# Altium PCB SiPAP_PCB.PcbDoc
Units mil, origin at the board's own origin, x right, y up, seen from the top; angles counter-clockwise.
Board outline 4000 x 3000 mil, 2 copper layers (Top Layer, Bottom Layer); 76 components, 74 nets, 268 pads, 135 vias.
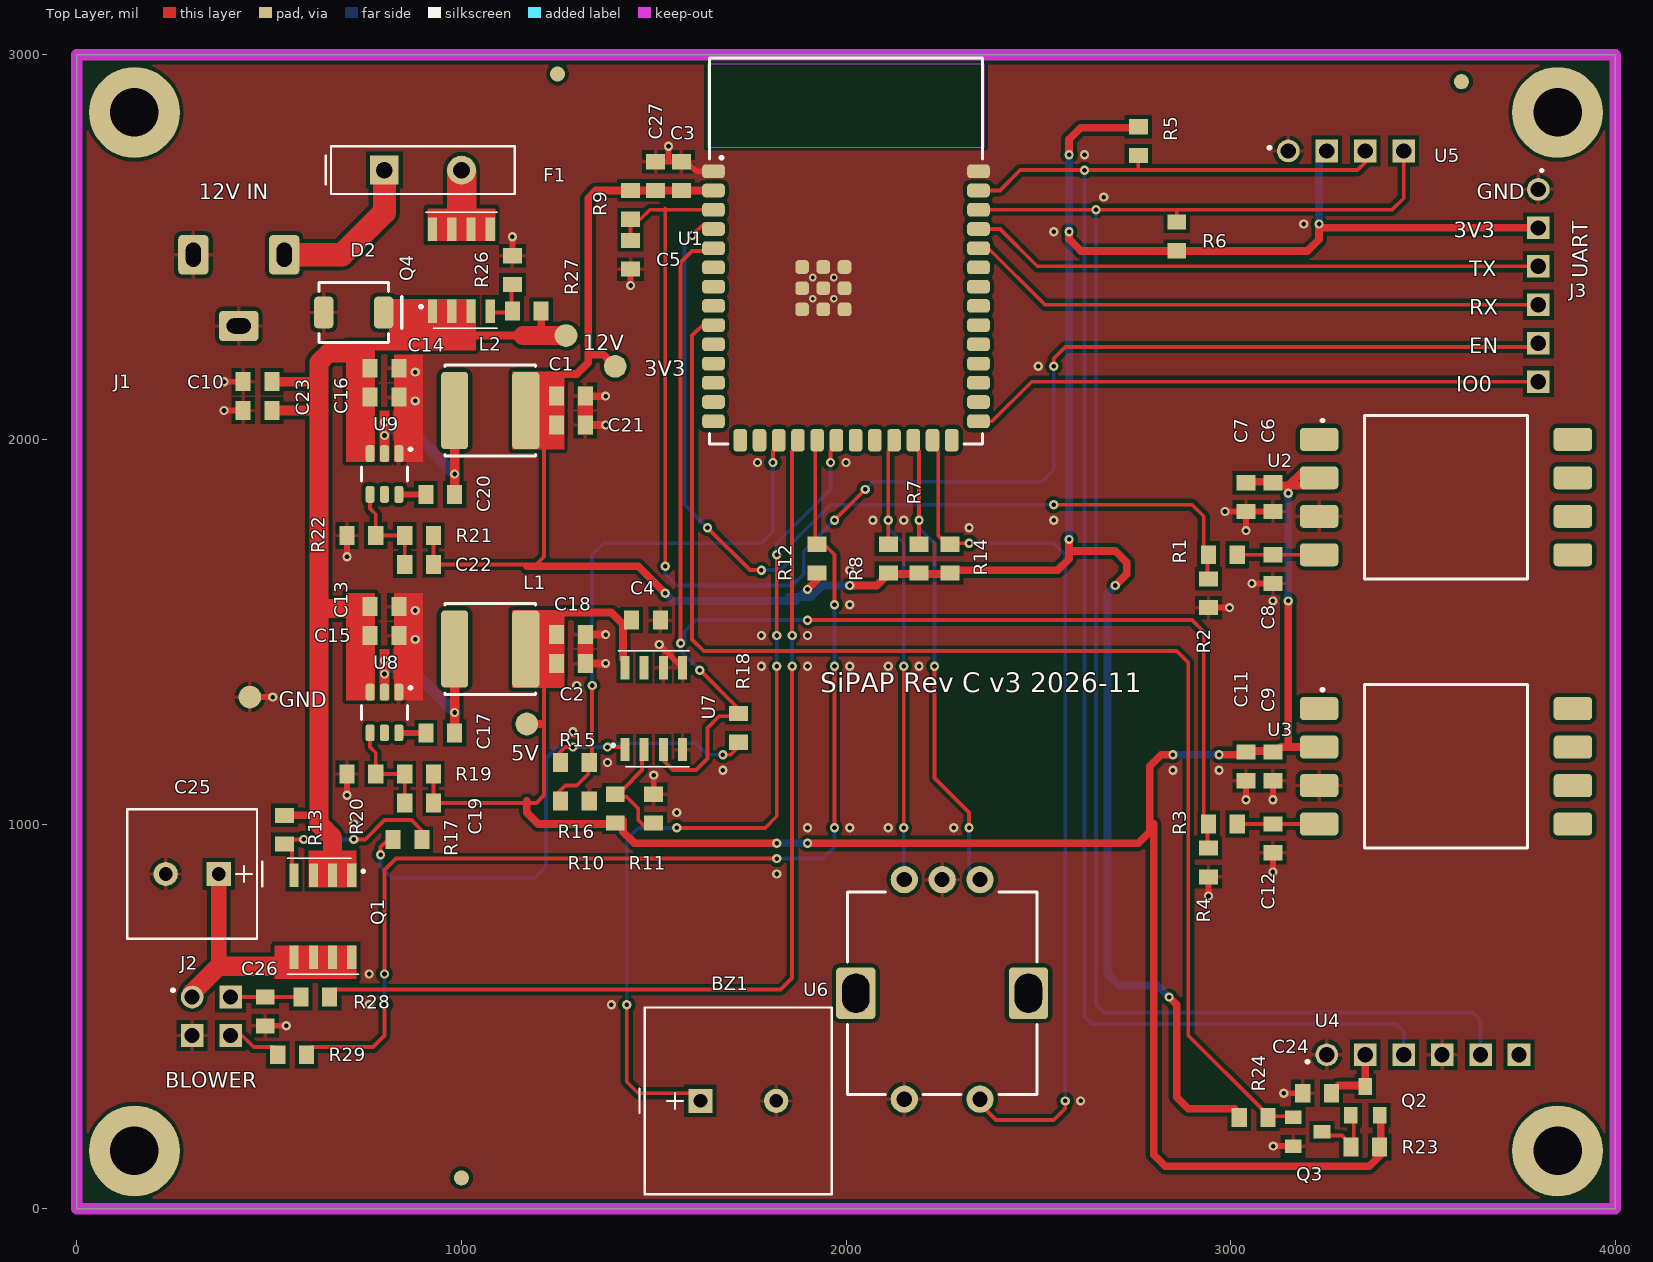
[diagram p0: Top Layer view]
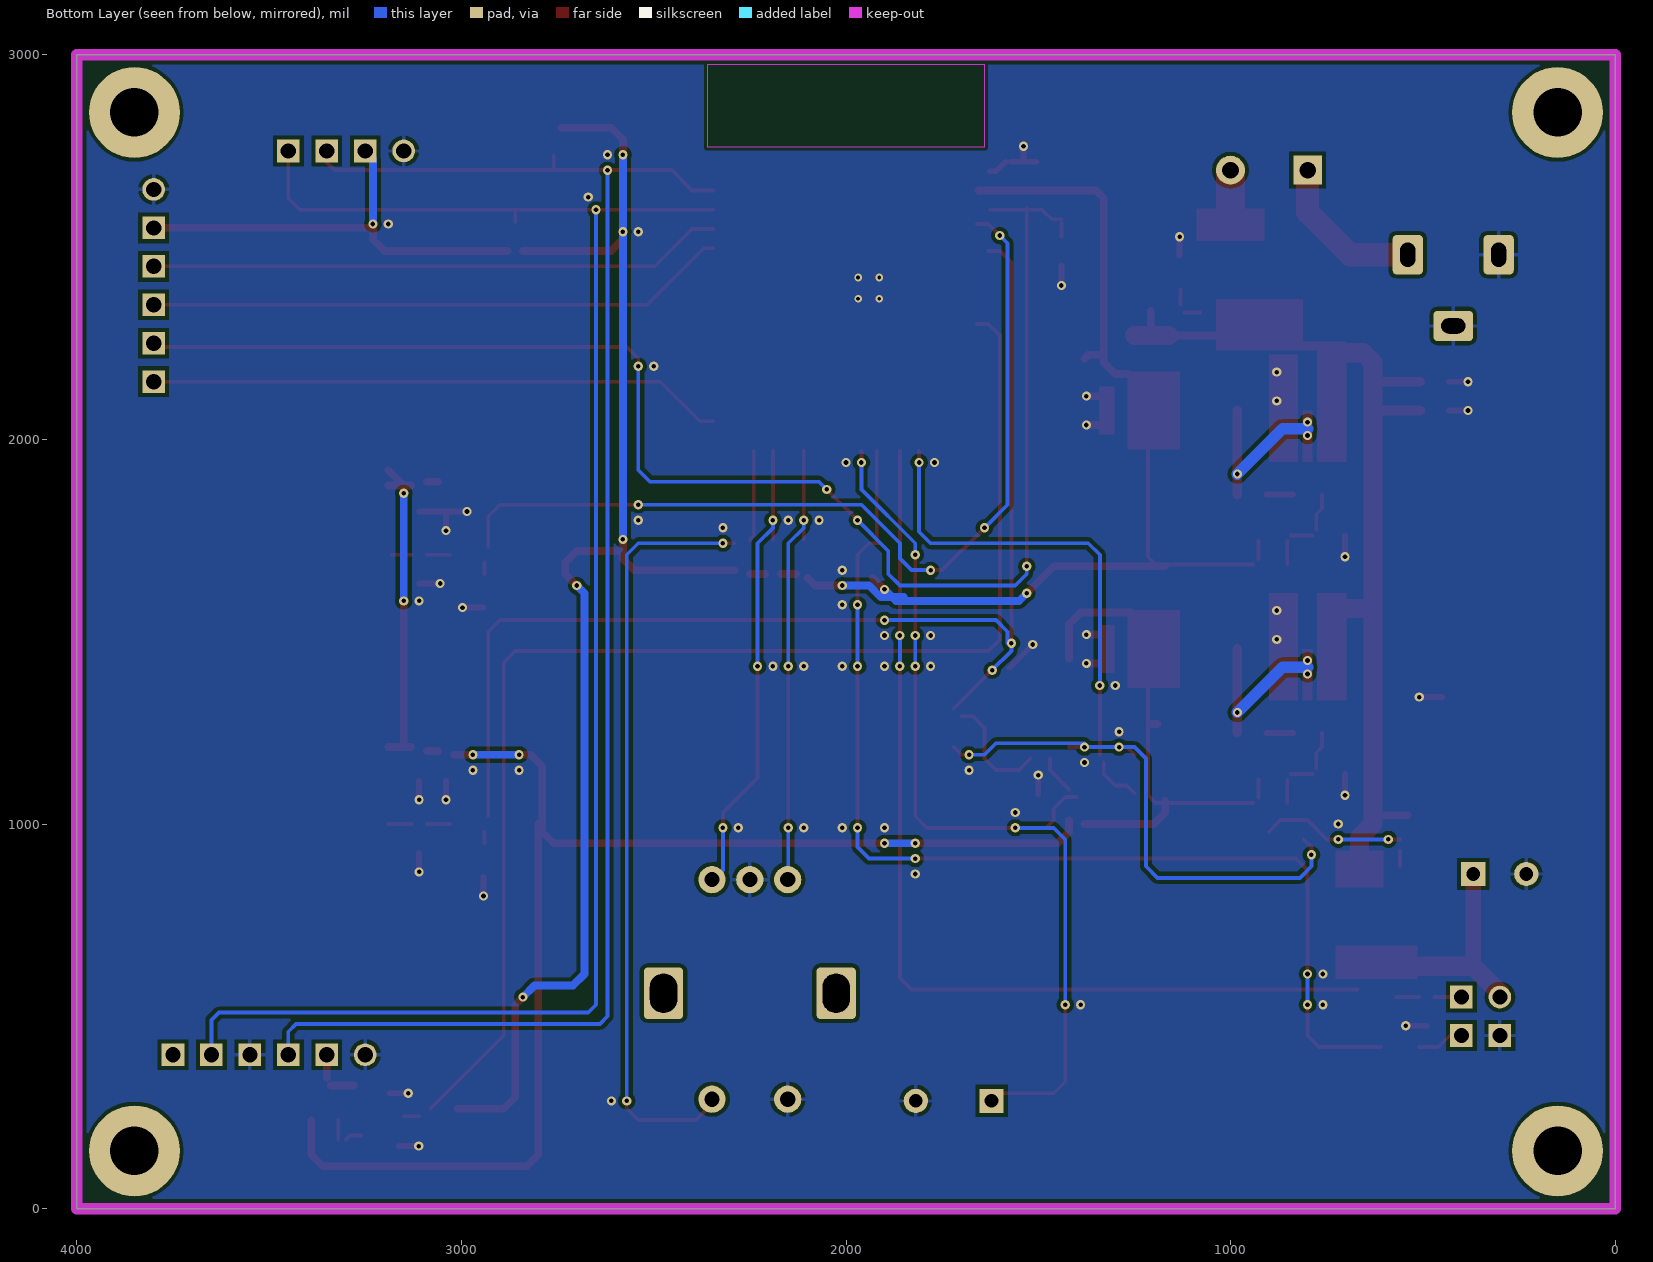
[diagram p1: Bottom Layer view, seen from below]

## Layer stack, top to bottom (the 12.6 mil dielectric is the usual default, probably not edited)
Top Solder: solder mask 0.4, Solder Resist, Dk 3.5
Top Layer: signal copper 1.4
Dielectric 1: dielectric 12.6, FR-4, Dk 4.8
Bottom Layer: signal copper 1.4
Bottom Solder: solder mask 0.4, Solder Resist, Dk 3.5

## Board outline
0,0 4000,0 4000,3000 0,3000

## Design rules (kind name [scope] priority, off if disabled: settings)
Clearance [All] p1: gap=10 ignorepadtopadclearanceinfootprint=FALSE
Height [All] p1: minheight=0 maxheight=1250 prefheight=500
HoleSize [All] p1: absolutevalues=TRUE maxlimit=150 minlimit=1 maxpercent=80.000 minpercent=20.000
MinimumSolderMaskSliver [All] p1: minsoldermaskwidth=4 // JLCPCB soldermask bridge 0.10 mm (1 oz, green)
PolygonConnect PolyConnect_U1_EPAD_Direct [InComponent('U1')] p1: connectstyle=Direct reliefconductorwidth=10 reliefentries=4 polygonreliefangle="90 Angle" airgapwidth=10
PolygonConnect PolyConnect_Vias_Direct [IsVia] p2: connectstyle=Direct reliefconductorwidth=10 reliefentries=4 polygonreliefangle="90 Angle" airgapwidth=10
PolygonConnect [All] p3: connectstyle=Relief reliefconductorwidth=10 reliefentries=4 polygonreliefangle="90 Angle" airgapwidth=10
RoutingCorners [All] p1: cornerstyle=45-Degree minsetback=10 maxsetback=100
RoutingVias [All] p1: holewidth=12 width=24 viastyle="Through Hole" minholewidth=10 minwidth=20 maxholewidth=16 maxwidth=32
SilkToSilkClearance [All] p1: silktosilkclearance=6 // JLCPCB silk spacing 0.15 mm
SilkToSolderMaskClearance [IsPad] p1: minsilkscreentomaskgap=6 clearancetoexposedcopper=TRUE // JLCPCB: silkscreen to pad >= 0.15 mm
SolderMaskExpansion TentedVias [IsVia] p1: expansion=-30 istentingtop=FALSE
SolderMaskExpansion [All] p2: expansion=0 istentingtop=FALSE
SupplyNets "Schematic Supply Nets_3" [InNet('3V3')] p1: voltage=0.000
SupplyNets "Schematic Supply Nets_2" [InNet('GND')] p2: voltage=0.000
SupplyNets "Schematic Supply Nets_1" [InNet('VIN12V')] p3: voltage=0.000
SupplyNets "Schematic Supply Nets" [InNet('5V')] p4: voltage=0.000
ViasUnderSMD NoViaInPad [All] p1: allowed=FALSE
Width [Not (InNet('VIN12V') Or InNet('VIN_RAW') Or InNet('VIN_FUSED') Or InNet('BLOWER_V12') Or InNet('5V') Or InNet('3V3') Or InNet('GND') Or InNet('SW5') Or InNet('SW3'))] p1: maxlimit=25 minlimit=10 preferedwidth=10 // signals 10 mil; BST 15; SFM_5V 20
Width Width_Power12V [InNet('VIN12V') Or InNet('VIN_RAW') Or InNet('VIN_FUSED') Or InNet('BLOWER_V12')] p2: maxlimit=80 minlimit=20 preferedwidth=50 // 12 V path 50-60 mil + copper regions on MOSFET pins
Width Width_Rails [InNet('5V') Or InNet('3V3') Or InNet('GND') Or InNet('SW5') Or InNet('SW3')] p3: maxlimit=60 minlimit=10 preferedwidth=20 // 5V/3V3 rails 20 mil (FB Kelvin sense 10 mil); GND stubs 15-20; SW node 25-30 (TI SLVSD26C 7.4.1: SW short and wide)
24 further rules are at their usual default settings.

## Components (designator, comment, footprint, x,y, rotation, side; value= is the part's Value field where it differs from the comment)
BZ1 "PS1240P02BT" BUZZER_TDK_PS1240 1720,280 r0 top
C1 "22uF 16V" R_0805 1285,2112.5 r0 top
C2 "22uF 16V" R_0805 1285,1417.5 r0 top
C3 "100nF" R_0805 1572,2684.5 r90 top
C4 "100nF" R_0805 1480,1530 r0 top
C5 "1uF" R_0805 1440,2480 r270 top
C6 "1uF" R_0805 3110,1850 r270 top
C7 "10nF" R_0805 3040,1850 r270 top
C8 "470pF" R_0805 3110,1662.6 r270 top
C9 "1uF" R_0805 3110,1150 r270 top
C10 "10uF 35V" R_0805 470,2150 r180 top
C11 "10nF" R_0805 3040,1150 r270 top
C12 "470pF" R_0805 3110,962.6 r270 top
C13 "10uF 35V" R_0805 800,1565 r0 top
C14 "10uF 35V" R_0805 800,2185 r0 top
C15 "100nF" R_0805 800,1490 r0 top
C16 "100nF" R_0805 800,2110 r0 top
C17 "100nF" R_0805 945,1236.85 r0 top
C18 "22uF 16V" R_0805 1285,1492.5 r0 top
C19 "75pF C0G" R_0805 890,1055 r180 top
C20 "100nF" R_0805 945,1856.85 r0 top
C21 "22uF 16V" R_0805 1285,2037.5 r0 top
C22 "56pF C0G" R_0805 890,1675 r180 top
C23 "22uF 25V" R_0805 470,2075 r180 top
C24 "100nF" R_0805 3225,300 r180 top
C25 "220uF 25V" CAP_RAD_D8_P3.5 300,870 r180 top
C26 "1uF" R_0805 490,512.6 r270 top
C27 "22uF 16V" R_0805 1505,2684.5 r90 top
D2 "SMBJ13A TVS" DIOM_SMB_DO-214AA_BOURNS 720,2330 r180 top
F1 "MF-R400 4A PTC" PTC_RADIAL_MF-R300 900,2700 r0 top
J1 "PJ-102AH 12V IN" CUI_PJ-102AH 0,2480 r0 top
J2 "Blower cable" CONN_HEADER_4_2X2 300,450 r0 top
J3 "Prog UART" CONN_HEADER_6 3800,2650 r270 top
L1 "15uH SRN6045TA-150M" IND_BOURNS_SRN6045TA 1074.9,1455 r90 top
L2 "10uH SRN6045TA-100M" IND_BOURNS_SRN6045TA 1074.9,2075 r90 top
Q1 "AO4407A" SOIC-8 640,760 r270 top
Q2 "AO3401A" SOT-23 3350,280 r0 top
Q3 "2N7002" SOT-23 3200,200 r270 top
Q4 "AO4407A" SOIC-8 1000,2440 r90 top
R1 "10k" R_0805 2980,1700 r180 top
R2 "20k" R_0805 2942.6,1600 r270 top
R3 "10k" R_0805 2980,1000 r180 top
R4 "20k" R_0805 2942.6,900 r270 top
R5 "4.7k" R_0805 2760,2775.4 r270 top
R6 "4.7k" R_0805 2860,2528 r90 top
R7 "10k" R_0805 2190,1690 r90 top
R8 "10k" R_0805 2110,1690 r90 top
R9 "10k" R_0805 1440,2609.7 r270 top
R10 "47k" R_0805 1400,1040 r90 top
R11 "10k" R_0805 1500,1040 r90 top
R12 "10k" R_0805 1925,1690 r90 top
R13 "10k" R_0805 540,985 r90 top
R14 "10k" R_0805 2270,1690 r90 top
R15 "1M" R_0805 1295,1160 r0 top
R16 "330k" R_0805 1295,1060 r0 top
R17 "10k" R_0805 860,960 r180 top
R18 "1M" R_0805 1720,1250 r90 top
R19 "100k 1%" R_0805 890,1130 r180 top
R20 "13.3k 1%" R_0805 740,1130 r180 top
R21 "100k 1%" R_0805 890,1750 r180 top
R22 "22.1k 1%" R_0805 740,1750 r180 top
R23 "100k" R_0805 3350,160 r180 top
R24 "10k" R_0805 3060,237.4 r0 top
R26 "10k" R_0805 1132.6,2440 r90 top
R27 "10k" R_0805 1170,2333.7 r0 top
R28 "1k" R_0805 620,550 r180 top
R29 "1k" R_0805 560,400 r0 top
U1 "ESP32-S3-WROOM-1-N8R8" ESP32-S3-WROOM-1_DS 2000,2490 r0 top
U2 "MPXV5010GC6U (primary)" MPXV5010GC6U_482A 3560,1850 r180 top
U3 "MPXV5010GC6U (redundant)" MPXV5010GC6U_482A 3560,1150 r180 top
U4 "SFM3300-D" CONN_HEADER_6 3250,400 r0 top
U5 "OLED 0.96in I2C" CONN_HEADER_4 3150,2750 r0 top
U6 "PEC11R-4225F-S0024" PEC11R-4xxxF-S_DS 2250,560 r180 top
U7 "LM393" SOIC-8 1500,1300 r90 top
U8 "TPS54202 (5V)" TI_DDC0006A_SOT23-6 800,1290 r270 top
U9 "TPS54202 (3V3)" TI_DDC0006A_SOT23-6 800,1910 r270 top

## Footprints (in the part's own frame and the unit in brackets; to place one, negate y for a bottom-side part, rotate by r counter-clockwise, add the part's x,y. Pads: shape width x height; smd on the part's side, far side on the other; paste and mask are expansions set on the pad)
BUZZER_TDK_PS1240 [mil] "TDK PS1240P02BT piezo buzzer (TDK PS series p2-3: dia 12.2, H 6.5, pitch 5.0, pin 0.65). Hole 0.9 mm."
  rect 63x63 hole 35.4: 1(-98.42,0)
  round 63 hole 35.4: 2(98.42,0)
  silkscreen extent -257,-243 243,243, body extent -240,-240 240,240, height 256
CAP_RAD_D8_P3.5 [mil] "Radial aluminium electrolytic D8 mm, lead pitch 3.5 mm, lead 0.6 mm (Panasonic EEU-FC1E221, FC-A series p6). Pad 1 (square) = +. Hole 0.9 mm."
  rect 63x63 hole 35.4: 1(-68.9,0)
  round 63 hole 35.4: 2(68.9,0)
  silkscreen extent -182,-169 169,169, body extent -157,-157 157,157, height 453
CONN_HEADER_4 [mm] "4-pin THT header, single row, 2.54mm pitch (OLED / buck module)"
  round 1.5 hole 1: 1(0,0)
  rect 1.5x1.5 hole 1: 2(2.54,0) 3(5.08,0) 4(7.62,0)
  body extent -1.27,-1.27 8.89,1.27, height 8.5
CONN_HEADER_4_2X2 [mm] "4-pin THT header, 2x2, 2.54mm pitch (blower cable connector)"
  round 1.5 hole 1: 1(0,2.54)
  rect 1.5x1.5 hole 1: 2(0,0) 3(2.54,2.54) 4(2.54,0)
  body extent -1.27,-1.27 3.81,3.81, height 8.5
CONN_HEADER_6 [mm] "6-pin THT header 2.54mm pitch, single row (for SFM3300-D cable connector)"
  round 1.5 hole 1: 1(0,0)
  rect 1.5x1.5 hole 1: 2(2.54,0) 3(5.08,0) 4(7.62,0) 5(10.16,0) 6(12.7,0)
  body extent -1.27,-1.27 13.97,1.27, height 8.5
CUI_PJ-102AH [mm] "Custom, 3 pads; custom lands, density N (nominal); from Same Sky PJ-102AH datasheet (09/12/2024), Recommended PCB Layout Top View, p. 2; Same Sky PJ-102AH DC jack, 2.0 mm pin, 5 A. Layout p2. Origin = plug-entry face on jack axis (place at board edge). Pin1 centre (+), pin2 sleeve, pin3 switch. Slots 1.0x1.6."
  rrect25% 2x2.6 hole 1 slot 1.6 at 90 deg: 1(13.7,0) 2(7.7,0)
  rrect25% 2.6x2 hole 1 slot 1.6 at 0 deg: 3(10.7,-4.7)
  Keep-Out Layer lines w0.762: 0,-5.08 0,5.08
  body extent 0,-4.5 14.4,4.5, height 11
DIOM_SMB_DO-214AA_BOURNS [mm] "Custom, 2 pads; custom lands, density N (nominal); from Bourns SMBJ Series TVS datasheet, Recommended Footprint SMB (DO-214AA), p. 3; Bourns SMB (DO-214AA) recommended footprint p3. Pad1 = cathode (band), pad2 = anode."
  rrect39% 1.27x2.1 smd: 1(-1.98,0) 2(1.98,0)
  silkscreen extent -2.28,-1.97 2.28,1.97, body extent -2.3,-1.95 2.3,1.95, height 2.44
ESP32-S3-WROOM-1_DS [mm] "Custom, 41 pads; custom lands, density N (nominal); from ESP32-S3-WROOM-1 & WROOM-1U Datasheet, v1.8, Figure 11-1 Recommended PCB Land Pattern, p. 45; Espressif datasheet v1.8 Fig 11-1. Origin = module centre. Antenna area = top 6 mm: keep copper out."
  rrect50% 1.5x0.9 smd: 1(-8.75,5.26) 2(-8.75,3.99) 3(-8.75,2.72) 4(-8.75,1.45) 5(-8.75,0.18) 6(-8.75,-1.09) 7(-8.75,-2.36) 8(-8.75,-3.63) 9(-8.75,-4.9) 10(-8.75,-6.17) 11(-8.75,-7.44) 12(-8.75,-8.71) 13(-8.75,-9.98) 14(-8.75,-11.25) 27(8.75,-11.25) 28(8.75,-9.98) 29(8.75,-8.71) 30(8.75,-7.44) 31(8.75,-6.17) 32(8.75,-4.9) 33(8.75,-3.63) 34(8.75,-2.36) 35(8.75,-1.09) 36(8.75,0.18) 37(8.75,1.45) 38(8.75,2.72) 39(8.75,3.99) 40(8.75,5.26)
  rrect50% 0.9x1.5 smd: 15(-6.985,-12.5) 16(-5.715,-12.5) 17(-4.445,-12.5) 18(-3.175,-12.5) 19(-1.905,-12.5) 20(-0.635,-12.5) 21(0.635,-12.5) 22(1.905,-12.5) 23(3.175,-12.5) 24(4.445,-12.5) 25(5.715,-12.5) 26(6.985,-12.5)
  rrect50% 0.9x0.9 smd: 41(-2.9,-3.86) 41(-2.9,-2.46) 41(-2.9,-1.06) 41(-1.5,-3.86) 41(-1.5,-2.46) 41(-1.5,-1.06) 41(-0.1,-3.86) 41(-0.1,-2.46) 41(-0.1,-1.06)
  Keep-Out Layer region: -9.144,6.858 9.144,6.858 9.144,12.319 -9.144,12.319
  Keep-Out Layer lines w0.762: -9.652,12.954 9.652,12.954
  silkscreen extent -9,-12.75 9,12.75, body extent -9,-12.75 9,12.75, height 3.1
IND_BOURNS_SRN6045TA [mm] "Custom, 2 pads; custom lands, density N (nominal); from Bourns SRN6045TA Series datasheet, Recommended Layout, p. 1; Bourns SRN6045TA power inductor, recommended layout p1 (6.0x6.0 body, 4.25+/-0.3 tall)."
  rrect28% 5.1x1.8 smd: 1(0,2.35) 2(0,-2.35)
  silkscreen extent -3,-3 3,3, body extent -3,-3 3,3, height 4.55
MPXV5010GC6U_482A [mm] "Custom, 8 pads; custom lands, density N (nominal); from Motorola MPX5010/MPXV5010G Series datasheet (MPX5010/D), 2001, Figure 5 SOP Footprint (Case 482), p. 6; Case 482A land pattern per datasheet Fig 5 p6; pin order per Case 482A top view p7. Height 13.21 max incl. port."
  rrect33% 2.54x1.52 smd: 1(8.38,-3.81) 2(8.38,-1.27) 3(8.38,1.27) 4(8.38,3.81) 5(-8.38,3.81) 6(-8.38,1.27) 7(-8.38,-1.27) 8(-8.38,-3.81)
  silkscreen extent -5.4,-5.4 5.4,5.4, body extent -9.21,-5.4 9.21,5.4, height 13.21
PEC11R-4xxxF-S_DS [mm] "Custom, 6 pads; custom lands, density N (nominal); from Bourns PEC11R Series 12 mm Incremental Encoder datasheet, PEC11R-4xxxF-Sxxxx recommended PCB layout, p. 2; Bourns PEC11R-4xxxF-Sxxxx PCB layout (datasheet p2). Origin = shaft centre. A-C-B 2.5mm pitch 7.5mm below, switch pins 7.0mm above, 2 plated mounting slots 1.8x2.6 (13.2 outer), pad MP = mechanical."
  round 1.8 hole 1: 1(-2.5,-7.5) 2(2.5,-7.5) 3(0,-7.5) 4(-2.5,7) 5(2.5,7)
  rrect19% 2.6x3.4 hole 1.8 slot 2.6 at 90 deg: MP(-5.7,0) MP(5.7,0)
  silkscreen extent -6.25,-6.7 6.25,6.7, body extent -6.25,-6.7 6.25,6.7, height 31.5
PTC_RADIAL_MF-R300 [mil] "Bourns MF-R300 radial PPTC (datasheet p3: A 12.0 max, B 18.3 max tall, C 5.1 lead spacing, E 3.0 max, lead dia 0.81). Hole 1.1 mm."
  rect 75x75 hole 43.3: 1(-100.39,0)
  round 75 hole 43.3: 2(100.39,0)
  silkscreen extent -253,-62 239,62, body extent -283,-59 283,59, height 976
R_0805 [mm] "Standard 0805 SMD chip resistor land pattern (IPC nominal)"
  rect 1x1.25 smd: 1(-0.95,0) 2(0.95,0)
  body extent -1,-0.63 1,0.63, height 1.25
SOIC-8 [mm] "Standard SOIC-8, 1.27mm pitch, 3.9mm body (LM393 comparator)"
  rect 1.55x0.6 smd: 1(-2.7,1.905) 2(-2.7,0.635) 3(-2.7,-0.635) 4(-2.7,-1.905) 5(2.7,-1.905) 6(2.7,-0.635) 7(2.7,0.635) 8(2.7,1.905)
  silkscreen extent -3.83,-2.35 3.83,2.35, body extent -3,-2.45 3,2.45, height 1.75
SOT-23 [mm] "Standard SOT-23-3, 0.95mm pitch (AO3401A P-MOSFET, pin1=G pin2=S pin3=D)"
  rect 0.9x1.1 smd: 1(-0.95,-0.95) 2(0.95,-0.95) 3(0,0.95)
  body extent -1.45,-0.65 1.45,0.65, height 1.12
TI_DDC0006A_SOT23-6 [mm] "Custom, 6 pads; custom lands, density N (nominal); from TI TPS54202 datasheet SLVSD26C, C (Feb 2026), DDC0006A Example Board Layout, p. 29; TI DDC0006A (SOT-23-6, 1.1 max height) land pattern per TPS54202 datasheet p29."
  rrect50% 1.1x0.6 smd: 1(-1.35,0.95) 2(-1.35,0) 3(-1.35,-0.95) 4(1.35,-0.95) 5(1.35,0) 6(1.35,0.95)
  silkscreen extent -0.45,-1.53 0.45,1.53, body extent -0.8,-1.45 0.8,1.45, height 1.1

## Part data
BZ1: library part BUZZER_TDK_PS1240
C1 C2 C3 C4 C5 C6 C7 C8 C9 C11 C12 C26 C27: library part CAPACITOR
C10 C13 C14 C15 C16 C17 C18 C19 C20 C21 C22 C23 C24 R13 R19 R20 R21 R22 R23 R24 R26 R27: library part R_0805
C25: library part CAP_RAD_D8_P3.5
D2: library part DIOM_SMB_DO-214AA_BOURNS
F1: library part PTC_RADIAL_MF-R300
J1: library part CUI_PJ-102AH
J2: library part CONN_BLOWER4
J3: library part CONN_UART6
L1 L2: library part IND_BOURNS_SRN6045TA
Q1 Q4: library part SOIC-8
Q2 Q3: library part SOT-23
R1 R2 R3 R4 R5 R6 R7 R8 R9 R10 R11 R12 R14 R15 R16 R17 R18 R28 R29: library part RESISTOR
U1: library part ESP32-S3-WROOM-1
U2: library part MPXV5010GC6U_482A
U3: library part MPXV5010GC6U
U5: library part SSD1306_OLED_I2C
U6: library part PEC11R-4220F-S0024
U8 U9: library part TI_DDC0006A_SOT23-6

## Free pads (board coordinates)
  round 39.37 smd paste-25 mask+19.69: FID1(1250,2950) FID2(3600,2930) FID3(1000,80)
  round 236 hole 126: MH1(150,150) MH2(3850,150) MH3(150,2850) MH4(3850,2850)
  round 59 smd paste-40: TP1(1272,2270) TP2(1170,1260) TP3(1400,2190) TP4(450,1330)

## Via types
v1: diameter 24, hole 12, Top Layer to Bottom Layer, 131 vias
v2: diameter 20, hole 10, Top Layer to Bottom Layer, 4 vias

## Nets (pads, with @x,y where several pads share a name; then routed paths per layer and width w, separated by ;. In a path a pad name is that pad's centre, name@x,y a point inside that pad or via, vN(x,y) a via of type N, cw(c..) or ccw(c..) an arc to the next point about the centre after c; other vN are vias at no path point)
3V3: C1.1 C3.1 C21.1 C22.1 C27.1 J3.2 L2.2 pad.TP3 R5.1 R6.1 R7.1 R8.1 R9.1 R12.1 R14.1 R21.1 R24.1 U1.2 U5.2 | length 7490.1
  Top Layer w10: C22.1@927.4,1689 R21.1@927.4,1736 ; C22.1@941.4,1675 1195,1675 1215,1695 1215,1974.5
  Top Layer w20: 1170,1670 1460,1670 v1(1530,1600) ; 1267,2170 1300,2170 1330,2200 1330,2627.1 1350,2647.1 R9.1 C27.1 C3.1 U1.2 ; 1340,2220 1370,2220 pad.TP3@1380,2210 ; v1(1900,1610) R12.1@1930,1640 ; v1(2010,1620) 2080,1620 R8.1@2100,1640 ; R8.1@2130,1650 R7.1@2170,1650 ; R7.1@2210,1650 R14.1@2250,1650 ; R14.1@2290,1660 2550,1660 2580,1690 v1(2580,1740) ; v1(2580,2540) 2580,2520 2610,2490 R6.1@2840,2490 ; v1(2580,2740) 2580,2780 2610,2810 R5.1@2740,2810 ; 2590,1710 2700,1710 2730,1680 2730,1650 v1(2700,1620) ; v1(2840,550) 2860,530 2860,290 2890,260 R24.1@3010,260 ; R6.1@2880,2490 3200,2490 3230,2520 v1(3230,2560) ; 3240,2550 J3.2@3780,2550
  Bottom Layer w20: v1(1530,1600) 1550,1580 1870,1580 v1(1900,1610) ; 1850,1590 1910,1590 1940,1620 v1(2010,1620) ; v1(2580,1740) v1(2580,2740) ; v1(2700,1620) 2680,1600 2680,610 2710,580 2810,580 v1(2840,550) ; v1(3230,2560) U5.2@3230,2730
5V: C2.1 C4.1 C6.1 C7.1 C9.1 C11.1 C18.1 C19.1 L1.2 pad.TP2 Q2.2 R10.1 R19.1 R23.1 U2.2 U3.2 U7.8 | length 5451.9
  Top Layer w10: C19.1@927.4,1069 R19.1@927.4,1116 ; C19.1@941.4,1055 1195,1055 1215,1075 1215,1354.5
  Top Layer w20: 1170,1060 1170,1030 1200,1000 R10.1@1380,1000 ; pad.TP2@1190,1260 1210,1260 ; 1260,1550 1390,1550 1420,1520 U7.8@1420,1430 ; R10.1@1420,1010 1420,1002.5 1420,980 1450,950 v1(1820,950) ; v1(1900,950) 2760,950 2790,980 2790,1150 2820,1180 v1(2850,1180) ; 2800,1000 2800,140 2830,110 3360,110 3390,140 3390,160 Q2.2@3390,230 ; v1(2970,1180) C11.1@3020,1180 ; C11.1@3060,1190 C9.1@3090,1190 ; C7.1@3060,1890 C6.1@3090,1890 ; C9.1@3130,1200 U3.2@3190,1200 ; C6.1@3130,1880 U2.2@3190,1880 ; 3150,1210 v1(3150,1580) ; v1(3150,1860) 3150,1880 U2.2@3190,1920
  Bottom Layer w20: v1(1820,950) v1(1900,950) ; v1(2850,1180) v1(2970,1180) ; v1(3150,1580) v1(3150,1860)
BLOWER_FG: R12.2 R29.2 U1.19 | length 2889.7
  Top Layer w10: R29.2@610,420 770,420 800,450 v1(800,530) ; v1(800,610) 800,880 830,910 v1(1820,910) ; R12.2@1910,1730 1940,1730 1970,1700 v1(1970,1570) ; R12.2@1920,1740 U1.19@1920,1970 ; v1(1970,990) v1(1970,1410)
  Bottom Layer w10: v1(800,530) v1(800,610) ; v1(1820,910) 1940,910 1970,940 v1(1970,990) ; v1(1970,1410) v1(1970,1570)
BLOWER_FG_IN: J2.4 R29.1 | length 106.6
  Top Layer w10: J2.4@420,460 460,420 R29.1@510,420
BLOWER_PWM: R28.1 U1.18 | length 2572.4
  Top Layer w10: R28.1@670,570 1830,570 1860,600 v1(1860,1410) ; v1(1860,1490) 1860,1970
  Bottom Layer w10: v1(1860,1410) v1(1860,1490)
BLOWER_V12: C25.1 J2.1 Q1.5 Q1.6 Q1.7 Q1.8 | length 509.6
  Top Layer w40: 368.9,630 C25.1
  Top Layer w50: J2.1 300,561 369,630 530,630
BLOWER_VSR: C26.1 J2.3 R28.2 | length 110
  Top Layer w10: J2.3@420,550 C26.1@470,550 ; C26.1@510,550 R28.2@570,550
BOOT: J3.6 U1.27 | length 1498.1
  Top Layer w10: U1.27 2380,2047.1 2482.9,2150 J3.6
BST3: C20.1 U9.6 | length 70.2
  Top Layer w15: U9.6@837.4,1856.85 C20.1
BST5: C17.1 U8.6 | length 70.2
  Top Layer w15: U8.6@837.4,1236.85 C17.1
BUZZER_CTRL: BZ1.1 U1.20 | length 2235.3
  Top Layer w10: v1(1430,530) 1430,330 1460,300 BZ1.1@1600,300 ; v1(1560,990) 1790,990 1820,1020 v1(1820,1410) ; v1(1820,1490) v1(1820,1700) ; v1(1960,1940) 1960,1970
  Bottom Layer w10: v1(1430,530) 1430,960 1460,990 v1(1560,990) ; v1(1820,1410) v1(1820,1490) ; v1(1820,1700) 1820,1730 1960,1870 v1(1960,1940)
COMP_OUT: R15.1 R17.2 R18.1 U7.1 | length 1424.6
  Top Layer w10: v1(790,920) 790,940 R17.2@810,960 ; R15.1@1250,1180 1270,1200 v1(1290,1200) ; v1(1380,1200) U7.1@1420,1200 ; v1(1680,1180) 1700,1180 R18.1@1720,1200
  Bottom Layer w10: v1(790,920) 790,890 820,860 1190,860 1220,890 1220,1170 1250,1200 v1@1280,1200 ; v1(1290,1200) v1(1380,1200) ; v1@1380,1210 1610,1210 1640,1180 v1(1680,1180)
COMP_REF: R10.2 R11.1 U7.2 | length 231.4
  Top Layer w10: R10.2@1400,1070 1430,1070 1460,1040 1460,1010 R11.1@1480,990 ; R10.2@1420,1090 1470,1140 U7.2@1470,1170
EN: C5.1 J3.5 R9.2 U1.3 | length 3905.4
  Top Layer w10: C5.1@1440,2527.4 R9.2@1440,2562.3 ; R9.2 1465.2,2572.3 1490,2597.1 U1.3@1626,2597.1 ; v1(1530,1670) 1530,2600 ; v1(1970,1790) v1(2050,1870) ; v1(2540,2190) 2540,2210 2570,2240 J3.5@3780,2240
  Bottom Layer w10: v1(1530,1670) 1530,1650 1560,1620 1860,1620 1890,1650 1890,1710 v1(1970,1790) ; v1(2050,1870) 2070,1890 2510,1890 2540,1920 v1(2540,2190)
ENC_A: R7.2 U1.24 U6.1 | length 1193.8
  Top Layer w10: R7.2@2190,1740 v1(2190,1790) 2190,1970 ; v1(2230,1410) 2230,1120 2320,1030 v1(2320,990)
  Bottom Layer w10: v1(2190,1790) 2190,1770 2230,1730 v1(2230,1410) ; 2320,880 v1(2320,990)
ENC_B: R8.2 U1.23 U6.2 | length 1156.6
  Top Layer w10: R8.2@2110,1740 v1(2110,1790) 2110,1970 ; v1(2150,990) v1(2150,1410)
  Bottom Layer w10: v1(2110,1790) 2110,1770 2150,1730 v1(2150,1410) ; U6.2@2150,880 v1(2150,990)
ENC_SW: R14.2 U1.25 U6.4 | length 2201.4
  Top Layer w10: 2240,1970 2240,1750 R14.2@2250,1740 ; R14.2@2290,1730 v1(2320,1730) ; U6.4@2360,260 2390,230 2540,230 2570,260 v1(2570,280)
  Bottom Layer w10: v1(2320,1730) 2540,1730 2570,1700 v1(2570,280)
FB3: C22.2 R21.2 R22.1 U9.4 | length 215.2
  Top Layer w10: U9.4@762.6,1856.85 762.6,1820 777.4,1805.2 R22.1@777.4,1764 ; R22.1@787.4,1750 R21.2@842.6,1750 ; C22.2 R21.2@852.6,1736
FB5: C19.2 R19.2 R20.1 U8.4 | length 215.2
  Top Layer w10: U8.4@762.6,1236.85 762.6,1200 777.4,1185.2 R20.1@777.4,1144 ; R20.1@787.4,1130 R19.2@842.6,1130 ; C19.2 R19.2@852.6,1116
GATE: Q1.4 R13.1 R17.1 | length 413.1
  Top Layer w10: Q1.4@560,890 R13.1@560,930 ; R13.1@560,960 v1(590,960) ; v1(720,960) 750,960 800,1010 870,1010 R17.1@900,980
  Bottom Layer w10: v1(590,960) v1(720,960)
GND: BZ1.2 C1.2 C2.2 C3.2 C4.2 C5.2 C6.2 C7.2 C8.2 C9.2 C10.2 C11.2 C12.2 C13.2 C14.2 C15.2 C16.2 C18.2 C21.2 C23.2 C24.2 C25.2 C26.2 C27.2 D2.2 J1.2 J1.3 J2.2 J3.1 pad.TP4 Q3.2 R2.2 R4.2 R11.2 R16.2 R20.2 R22.2 R26.2 U1.1 U1.40 U1.41 U2.3 U3.3 U4.1 U4.4 U5.1 U6.3 U6.5 U7.4 U7.5 U7.6 U8.1 U9.1 | length 1513.2
  Top Layer w15: v1(382.91,2075) C23.2 ; v1(382.91,2150) C10.2 ; pad.TP4 v1(509.5,1330) ; C26.2 v1(544.61,475.2) ; v1(702.6,1075) R20.2 ; v1(702.6,1695) R22.2 ; R26.2 v1(1132.6,2527.09) ; v1(1440,2400) C5.2@1440,2452.6 ; R11.2 v1(1500,1127.09) ; C27.2 C3.2 ; v1(1514.49,1466.81) U7.5 ; 1538.5,2721.9 v1(1538.5,2762) ; C3.2@1585.2,2721.9 1610,2697.1 U1.1@1626,2697.1 ; v1(2942.6,812.91) R4.2 ; R2.2 v1(2997.21,1562.6) ; v1(2985.39,1812.6) 3040,1812.5 C6.2 ; v1(3040,1062.91) C11.2 ; v1(3040,1762.91) C7.2 ; v1(3055.39,1625.2) C8.2 ; v1(3110,875.51) C12.2 ; v1(3110,1062.91) C9.2 ; v1(3110.94,162.6) Q3.2 ; v1(3137.91,300) C24.2
  Top Layer w20: C2.2 v1(1375,1417.5) ; C18.2 v1(1375,1492.5) ; C21.2 v1(1375,2037.5) ; C1.2 v1(1375,2112.5)
  other v1: 2610,280 760,530 1390,530 760,610 1820,870 1900,990 2010,990 2110,990 2280,990 720,1000 1560,1030 1680,1140 2850,1140 2970,1140 1380,1160 1290,1240 1300,1360 1780,1410 1900,1410 2010,1410 2110,1410 2190,1410 880,1480 1780,1490 1900,1490 880,1555 2010,1570 3110,1580 2010,1660 2320,1770 2070,1790 2150,1790 2540,1790 1770,1940 2000,1940 880,2100 880,2175 2500,2190 2540,2540 3190,2560 2670,2630 2620,2740
  other v2: 1913.4,2365.6 1968.5,2365.6 1913.4,2420.7 1968.5,2420.7
I2C_SCL: R5.2 U1.39 U4.3 U5.3 | length 4210.3
  Top Layer w10: U1.39 2400,2647.1 2452.9,2700 v1(2620,2700) 2760,2700 ; R5.2 2760,2700 ; U5.3 3350,2720 3330,2700 2760,2700
  Bottom Layer w10: v1(2620,2700) 2620,500 2640,480 3430,480 3450,460 U4.3
I2C_SDA: R6.2 U1.38 U4.5 U5.4 | length 4446.2
  Top Layer w10: U1.38 v1(2650,2597.1) 2860,2597.1 ; R6.2 2860,2597.1 ; U5.4 3450,2627.1 3420,2597.1 2860,2597.1
  Bottom Layer w10: v1(2650,2597.1) 2650,530 2670,510 3630,510 3650,490 U4.5
NetU1_6: U1.6
NetU1_7: U1.7
NetU1_8: 
NetU1_10: U1.10
NetU1_11: U1.11
NetU1_12: U1.12
NetU1_13: 
NetU1_14: 
NetU1_15: U1.15
NetU1_16: 
NetU1_21: 
NetU1_22: 
NetU1_26: 
NetU1_28: 
NetU1_29: 
NetU1_30: 
NetU1_31: 
NetU1_32: 
NetU1_33: 
NetU1_34: 
NetU1_35: 
NetU2_1: 
NetU2_5: 
NetU2_6: 
NetU2_7: 
NetU2_8: 
NetU3_1: 
NetU3_5: 
NetU3_6: 
NetU3_7: 
NetU3_8: 
NetU4_6: 
NetU7_7: 
NetU8_5: 
NetU9_5: 
PRESS_PRI_ADC: R1.2 R2.1 U1.4 | length 2417.4
  Top Layer w10: v1(1600,2530) 1630,2560 1655.5,2560 U1.4@1660,2560 ; v1(1640,1770) 1750,1660 v1(1780,1660) ; v1(2540,1830) 2900,1830 2930,1800 R1.2@2930,1720 ; R2.1@2940,1650 R1.2@2940,1680
  Bottom Layer w10: v1(1600,2530) 1580,2510 1580,1830 v1(1640,1770) ; v1(1780,1660) 1830,1660 1860,1690 1860,1730 1960,1830 v1(2540,1830)
PRESS_PRI_RAW: C8.1 R1.1 U2.4 | length 110
  Top Layer w10: R1.1@3030,1700 C8.1@3090,1700 ; C8.1@3130,1700 3180,1700
PRESS_RED_ADC: R3.2 R4.1 R18.2 U1.5 U7.3 | length 3506.7
  Top Layer w10: U7.3@1520,1170 1550,1140 1610,1140 1640,1170 1640,1250 1670,1280 R18.2@1700,1280 ; v1(1570,1470) 1570,2460 1600,2490 U1.5@1630,2490 ; v1(1620,1400) R18.2@1720,1300 ; v1(1900,1530) 2900,1530 2930,1500 R3.2@2930,1020 ; R4.1@2940,950 R3.2@2940,980
  Bottom Layer w10: v1(1570,1470) 1570,1450 v1(1620,1400) ; v1@1580,1470 1580,1500 1610,1530 v1(1900,1530)
PRESS_RED_RAW: C12.1 R3.1 U3.4 | length 120
  Top Layer w10: R3.1@3030,1000 C12.1@3090,1000 ; C12.1@3130,1000 U3.4@3190,1000
RPP_G: Q4.4 R26.1 R27.1 | length 80
  Top Layer w10: Q4.4@1080,2330 R27.1@1120,2330 ; R27.1@1130,2350 R26.1@1130,2390
SAFETY_TRIP: R15.2 R16.1 U1.17 | length 1355.6
  Top Layer w10: R16.1@1250,1080 1270,1100 1300,1100 1330,1130 R15.2@1330,1160 ; R15.2@1340,1180 v1(1340,1360) ; v1(1810,1940) 1810,1970
  Bottom Layer w10: v1(1340,1360) 1340,1700 1370,1730 1780,1730 1810,1760 v1(1810,1940)
SFM_5V: C24.1 Q2.3 U4.2 | length 100
  Top Layer w20: C24.1@3280,320 Q2.3@3340,320 ; 3350,340 U4.2@3350,380
SFM_EN: Q3.1 R24.2 U1.9 | length 3456
  Top Layer w10: U1.9@1660,2300 1655.5,2300 1630,2300 1600,2270 1600,1480 1630,1450 2860,1450 2890,1420 2890,450 R24.2@3080,260 ; R24.2@3110,240 Q3.1@3150,240
SFM_G: Q2.1 Q3.3 R23.2 | length 94.1
  Top Layer w10: 3260,190 3290,190 R23.2@3300,180 ; R23.2@3320,180 Q2.1@3320,230
SW3: C20.2 L2.1 U9.2 | length 484.3
  Top Layer w25: C20.2 L2.1
  Bottom Layer w24: v1(800,2010) v1(800,2045)
  Bottom Layer w30: 800,2027.5 865,2027.5 v1@982.5,1910
  other v1: 982.4,1910
SW5: C17.2 L1.1 U8.2 | length 484.3
  Top Layer w25: C17.2 L1.1
  Bottom Layer w24: v1(800,1390) v1(800,1425)
  Bottom Layer w30: 800,1407.5 865,1407.5 v1@982.5,1290
  other v1: 982.4,1290
UART_RX: J3.4 U1.36 | length 1516.4
  Top Layer w10: U1.36 2370,2497.1 2517.1,2350 J3.4
UART_TX: J3.3 U1.37 | length 1495.7
  Top Layer w10: U1.37 2400,2547.1 2497.1,2450 J3.3
VIN12V: C10.1 C13.1 C14.1 C15.1 C16.1 C23.1 D2.1 pad.TP1 Q1.1 Q1.2 Q1.3 Q4.1 Q4.2 Q4.3 R13.2 R27.2 U8.3 U9.3 | length 2082.4
  Top Layer w20: R13.2 630,1022.4 ; 1037,2270 1187.4,2270 1207.4,2290 R27.2
  Top Layer w25: C23.1 630,2075 ; C10.1 630,2150
  Top Layer w50: 630,1560 700,1560 ; 665,930 665,965 630,1000 630,2200 655,2225 700,2225 ; 1160,2270 pad.TP1@1250,2270
VIN_FUSED: F1.2 Q4.5 Q4.6 Q4.7 Q4.8
VIN_RAW: F1.1 J1.1 | length 415.6
  Top Layer w60: J1.1 689.4,2480 799.6,2590.2 F1.1
pads on no net: U1.8 U1.13 U1.14 U1.16 U1.21 U1.22 U1.26 U1.28 U1.29 U1.30 U1.31 U1.32 U1.33 U1.34 U1.35 U2.1 U2.5 U2.6 U2.7 U2.8 U3.1 U3.5 U3.6 U3.7 U3.8 U4.6 U6.MP U7.7 U8.5 U9.5

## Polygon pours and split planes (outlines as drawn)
GND on Bottom Layer "Bottom Layer-GND" (solid, remove dead copper, pour order 0): 0,0 4000,0 4000,3000 0,3000
GND on Top Layer "Top Layer-GND" (solid, remove dead copper, pour order 1): 0,0 4000,0 4000,3000 0,3000

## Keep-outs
Keep-Out Layer:
  lines w30: 0,2280 0,0 4000,0 4000,3000 2380,3000 ; 0,2680 0,3000 1620,3000

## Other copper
Top Layer:
  region net BLOWER_V12: 515,684 515,598 727,598 727,684
  region net VIN12V: 603,930 603,836 727,836 727,930
  region net VIN12V: 700,2240 700,2210 775,2210 775,2240
  region net VIN12V: 700,2254 700,2232 1037,2232 1037,2254
  region net VIN12V: 813,2364 813,2254 1037,2254 1037,2364
  region net VIN_FUSED: 963,2600 963,2700 1038,2700 1038,2600 1088,2600 1088,2516 912,2516 912,2600
  region net GND: 1302.9,1393 1341.9,1393 1341.9,1517 1302.9,1517
  region net 5V: 1132,1354.5 1267,1354.5 1267,1555.5 1132,1555.5
  region net SW5: 788,1321.5 812,1321.5 812,1455 788,1455
  region net GND: 825,1321.5 900,1321.5 900,1600 825,1600
  region net VIN12V: 700,1321.5 775,1321.5 775,1600 700,1600
  region net GND: 1302.9,2013 1341.9,2013 1341.9,2137 1302.9,2137
  region net 3V3: 1132,1974.5 1267,1974.5 1267,2175.5 1132,2175.5
  region net SW3: 788,1941.5 812,1941.5 812,2075 788,2075
  region net GND: 825,1941.5 900,1941.5 900,2220 825,2220
  region net VIN12V: 700,1941.5 775,1941.5 775,2220 700,2220

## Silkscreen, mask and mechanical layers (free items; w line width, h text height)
Top Overlay:
  lines w6: 414.9,870 454.9,870 ; 434.9,850 434.9,890 ; 1535.58,280 1575.58,280 ; 1555.58,260 1555.58,300
  lines w10: 845,2290 845,2370
  lines w14: 249.7,568.13 250.7,568.13 ; 744.57,877.24 745.57,877.24 ; 866.97,1354.09 867.97,1354.09 ; 866.97,1974.09 867.97,1974.09 ; 894.43,2344.65 895.43,2344.65 ; 1394.43,1204.65 1395.43,1204.65 ; 1675.51,2732.59 1676.51,2732.59 ; 3100.26,2758.68 3101.26,2758.68 ; 3199.7,381.87 3200.7,381.87 ; 3238.26,1349.24 3239.26,1349.24 ; 3238.26,2049.24 3239.26,2049.24 ; 3808.18,2699.24 3809.18,2699.24
  text "12V IN" at 316.87,2624.01 h40
  text "GND" at 3640.18,2624.01 h40
  text "3V3" at 3580.37,2524.01 h40
  text "TX" at 3620.35,2424.01 h40
  text "UART" at 3928.39,2418.69 h40 r90
  text "RX" at 3620.35,2324.01 h40
  text "12V" at 1315.12,2231.51 h40
  text "EN" at 3620.35,2224.01 h40
  text "3V3" at 1475,2164.01 h40
  text "IO0" at 3587.03,2124.01 h40
  text "SiPAP Rev C v3 2026-11" at 1933.67,1342.61 h50
  text "GND" at 525,1304.01 h40
  text "5V" at 1130.18,1164.01 h40
  text "BLOWER" at 230.2,314.01 h40
Mechanical 13:
  lines w3.94: 0,2302.83 0,2657.17 566.93,2657.17 566.93,2302.83 0,2302.83
Mechanical 15:
  lines w1.97: 0,2245.75 0,2667 588.58,2667 588.58,2245.75 0,2245.75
